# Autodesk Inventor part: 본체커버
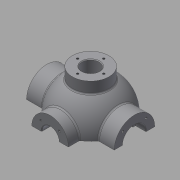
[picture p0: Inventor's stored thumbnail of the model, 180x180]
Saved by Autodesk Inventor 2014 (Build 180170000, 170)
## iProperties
Created: 2015-12
Part Number: 본체커버
Material: 일반
Document SubType Name: Modeling
Designer: mduedu
Density: 1 g/cm^3
Mass: 574.351 g
Surface Area: 450.515 cm^2
Volume: 211.938 cm^3
Appearance: 기본값
Author: mduedu
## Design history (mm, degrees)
sketch "스케치1"
  geometry: L1 (-53, 0)-(53, 0); A1 r 53 centre (0, 0) between (53, 0) and (-53, 0); 2 further points
  constraints: 2 coincident, 2 end point, 2 point on circle, 1 centre point, 1 horizontal, 1 midpoint
  dimensions: "d0" = 53 radius of A1
revolve "회전1" sketch "스케치1" stored, may be unused: angle "d2" = 90 deg
feature "쉘1" dims "d11" = 10
node "작업 평면1"
sketch "스케치2"
  geometry: C1 r 31 at (0, 0); 1 further point
  constraints: 1 centre point, 1 coincident
  dimensions: "d4" = 62 diameter of C1
extrude "돌출1" join sketch "스케치2" stored distance "d5" = 10; taper "d6" = 0 deg
node "작업 평면2"
sketch "스케치3"
  geometry: C1 r 28 at (0, 0); 1 further point
  constraints: 1 centre point, 1 coincident
  dimensions: "d8" = 56 diameter of C1
extrude "돌출2" join sketch "스케치3" stored distance "d9" = 10; taper "d10" = 0 deg
hole "구멍1" diameter "d14" = 35; stored, may be unused: countersink angle "d18" = 90 deg, drill point angle "d20" = 0 deg; dims "d12" = 10, "d13" = 10, "d15" = 6, "d16" = 4, "d17" = 2, "d19" = 16
hole "구멍2" diameter "d23" = 27; stored, may be unused: countersink angle "d27" = 90 deg, drill point angle "d29" = 0 deg; dims "d21" = 10, "d22" = 10, "d24" = 6, "d25" = 4, "d26" = 2, "d28" = 16
fillet "모깎기1" dims "d30" = 0.3
hole "구멍3" diameter "d33" = 26; stored, may be unused: countersink angle "d37" = 90 deg, drill point angle "d39" = 0 deg; dims "d31" = 10, "d32" = 10, "d34" = 6, "d35" = 4, "d36" = 2, "d38" = 16
chamfer "모따기1" distance "d40" = 1; stored, may be unused: second distance "d41" = 2, angle "d42" = 45 deg
sketch "스케치4"
  geometry: L1 (0, 0)-(0, -25); L2 (0, 0)-(-17.678, -17.678); A1 r 25 centre (0, 0) between (-17.678, -17.678) and (0, -25); 1 further point
  constraints: 4 end point, 2 point on circle, 1 centre point, 1 coincident, 1 vertical
  dimensions: "d43" = 50 diameter of A1; "d47" = 45 deg angle of L1 L2
hole "구멍4" sketch "스케치4" at (-17.678, -17.678) diameter "d49" = 3.242; stored, may be unused: countersink angle "d53" = 90 deg, drill point angle "d55" = 118 deg; dims "d50" = 11, "d51" = 4, "d52" = 2, "d54" = 13
sketch "스케치5"
  geometry: L1 (0, 0)-(0, -20); L2 (0, 0)-(-14.142, -14.142); A1 r 20 centre (0, 0) between (0, -20) and (-14.142, -14.142); 2 further points
  constraints: 4 end point, 2 coincident, 2 point on circle, 1 centre point, 1 vertical
  dimensions: "d59" = 40 diameter of A1; "d65" = 45 deg angle of L1 L2
hole "구멍5" sketch "스케치5" at (-14.142, -14.142) diameter "d67" = 3.242; stored, may be unused: countersink angle "d71" = 90 deg, drill point angle "d73" = 118 deg; dims "d68" = 8, "d69" = 4, "d70" = 2, "d72" = 10
node "작업 평면3"
sketch "스케치6"
  geometry: C1 r 65 at (0, 0); 1 further point
  constraints: 1 centre point, 1 coincident
  dimensions: "d78" = 130 diameter of C1
extrude "돌출3" join sketch "스케치6" distance "d80" = 10; taper "d81" = 0 deg
sketch "스케치7"
  geometry: C1 r 20 at (0, 0); 1 further point
  constraints: 1 centre point, 1 coincident
  dimensions: "d82" = 40 diameter of C1
extrude "돌출4" join sketch "스케치7" stored distance "d84" = 10; taper "d85" = 0 deg
sketch "스케치8"
  geometry: 2 further points
  constraints: 1 coincident
hole "구멍6" sketch "스케치8" at (0, 0) diameter "d86" = 20; stored, may be unused: countersink angle "d90" = 90 deg, drill point angle "d92" = 118 deg; dims "d87" = 7, "d88" = 40, "d89" = 5, "d91" = 10
fillet "모깎기2" dims "d93" = 0.3
sketch "스케치9"
  geometry: L1 (65, -75)-(-65, -75) reference; L2 (-45, -75)-(-38.245, -36.692); A1 r 53 centre (0, 0) between (42.988, 31) and (42.988, -31) reference; 1 further point
  constraints: 2 end point, 1 point on circle, 1 point on line
  dimensions: "d94" = 45 horizontal distance of L2.start point (0, 0); "d95" = 80 deg angle of L2 L1
feature "리브1" sketch "스케치9" dims "d96" = 1, "d97" = 8, "d98" = 0, "d99" = 0, "d100" = 1, "d101" = 1
sketch "스케치10"
  geometry: L1 (0, 0)-(0, -55); L2 (0, 0)-(-38.891, -38.891); A1 r 55 centre (0, 0) between (0, -55) and (-38.891, -38.891); 2 further points
  constraints: 4 end point, 2 coincident, 2 point on circle, 1 centre point, 1 vertical
  dimensions: "d105" = 110 diameter of A1; "d107" = 45 deg angle of L1 L2
hole "구멍7" sketch "스케치10" at (-38.891, -38.891) diameter "d109" = 10; stored, may be unused: countersink angle "d113" = 90 deg, drill point angle "d115" = 118 deg; dims "d110" = 7, "d111" = 40, "d112" = 5, "d114" = 10
fillet "모깎기3" dims "d120" = 3
fillet "모깎기4" dims "d121" = 3, "d122" = 3
fillet "모깎기5" dims "d123" = 3
fillet "모깎기6" dims "d124" = 3
sketch "스케치11"
  geometry: C1 r 5 at (-38.891, 38.891) reference; C2 r 5 at (38.891, 38.891) reference; C3 r 5 at (38.891, -38.891) reference; C4 r 5 at (-38.891, -38.891) reference; C5 r 20 at (0, 0) reference; C6 r 65 at (0, 0) reference; 1 further point
  constraints: 3 other
feature "엠보싱1" sketch "스케치11" dims "d125" = 0.5, "d126" = 0
sketch "스케치12"
  geometry: L1 (0, 100)-(0, -100); L2 (0, 100)-(-150, 100); L3 (-150, 100)-(-150, -100); L4 (-150, -100)-(0, -100); 2 further points
  constraints: 8 end point, 3 perpendicular, 1 coincident, 1 midpoint, 1 vertical
  dimensions: "d127" = 200 distance of L2.end L3.end; "d129" = 150 distance of L3.end L1.end
extrude "돌출5" cut sketch "스케치12" stored distance "d130" = 10; taper "d131" = 0 deg
sketch "스케치13"
  geometry: C1 r 7 at (0, -53); A1 r 53 centre (0, 0) between (-42.113, -32.179) and (42.113, -32.179) reference; 1 further point
  constraints: 1 centre point, 1 point on circle
  dimensions: "d132" = 14 diameter of C1
extrude "돌출6" join sketch "스케치13" distance "d133" = 5; taper "d134" = 0 deg
sketch "스케치14"
  geometry: C1 r 7 at (0, 0) reference; 1 further point
extrude "돌출7" cut sketch "스케치14" stored distance "d135" = 5; taper "d136" = 0 deg
sketch "스케치15"
  geometry: C1 r 2.25 at (0, 53); A1 r 7 centre (0, 53) between (6.965, 52.302) and (-6.965, 52.302) reference; 1 further point
  constraints: 1 centre point, 1 coincident
  dimensions: "d139" = 4.5 diameter of C1
extrude "돌출8" cut sketch "스케치15" stored distance "d141" = 5; taper "d142" = 0 deg
fillet "모깎기7" dims "d143" = 3
fillet "모깎기8" dims "d144" = 1
fillet "모깎기9" dims "d145" = 1
fillet "모깎기10" dims "d146" = 1
node "작업 평면4"
sketch "스케치16"
  geometry: C1 r 28 at (0, 0); 1 further point
  constraints: 1 centre point, 1 coincident
  dimensions: "d148" = 56 diameter of C1
extrude "돌출9" join sketch "스케치16" stored distance "d150" = 5; taper "d151" = 0 deg
hole "구멍8" diameter "d154" = 26; stored, may be unused: countersink angle "d158" = 90 deg, drill point angle "d160" = 118 deg; dims "d152" = 10, "d153" = 10, "d155" = 6, "d156" = 4, "d157" = 2, "d159" = 8
sketch "스케치17" dims "d161" = 40
  geometry: 3 further points
  constraints: 2 vertical alignment, 1 coincident, 2 other
hole "구멍9" sketch "스케치17" at (0, 20) diameter "d163" = 3.242; stored, may be unused: countersink angle "d167" = 90 deg, drill point angle "d169" = 118 deg; dims "d164" = 8, "d165" = 4, "d166" = 2, "d168" = 10
fillet "모깎기11" dims "d173" = 3
chamfer "모따기2" distance "d174" = 1; stored, may be unused: second distance "d175" = 2, angle "d176" = 45 deg
node "솔리드1"
mirror "대칭1"
mirror "대칭2"
pattern_circular "원형 패턴1" dims angle "d57" = 360 deg
mirror "대칭3"
pattern_circular "원형 패턴2" dims angle "d75" = 360 deg
pattern_circular "원형 패턴3" dims angle "d103" = 360 deg
pattern_circular "원형 패턴4" dims angle "d118" = 360 deg
pattern_circular "원형 패턴5" dims angle "d171" = 360 deg
node "투영된 루프1"
other parameters: "d3" = 67, "d7" = 62, "d77" = -85, "d147" = 62
